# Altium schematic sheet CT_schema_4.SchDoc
size 312 x 289 mm
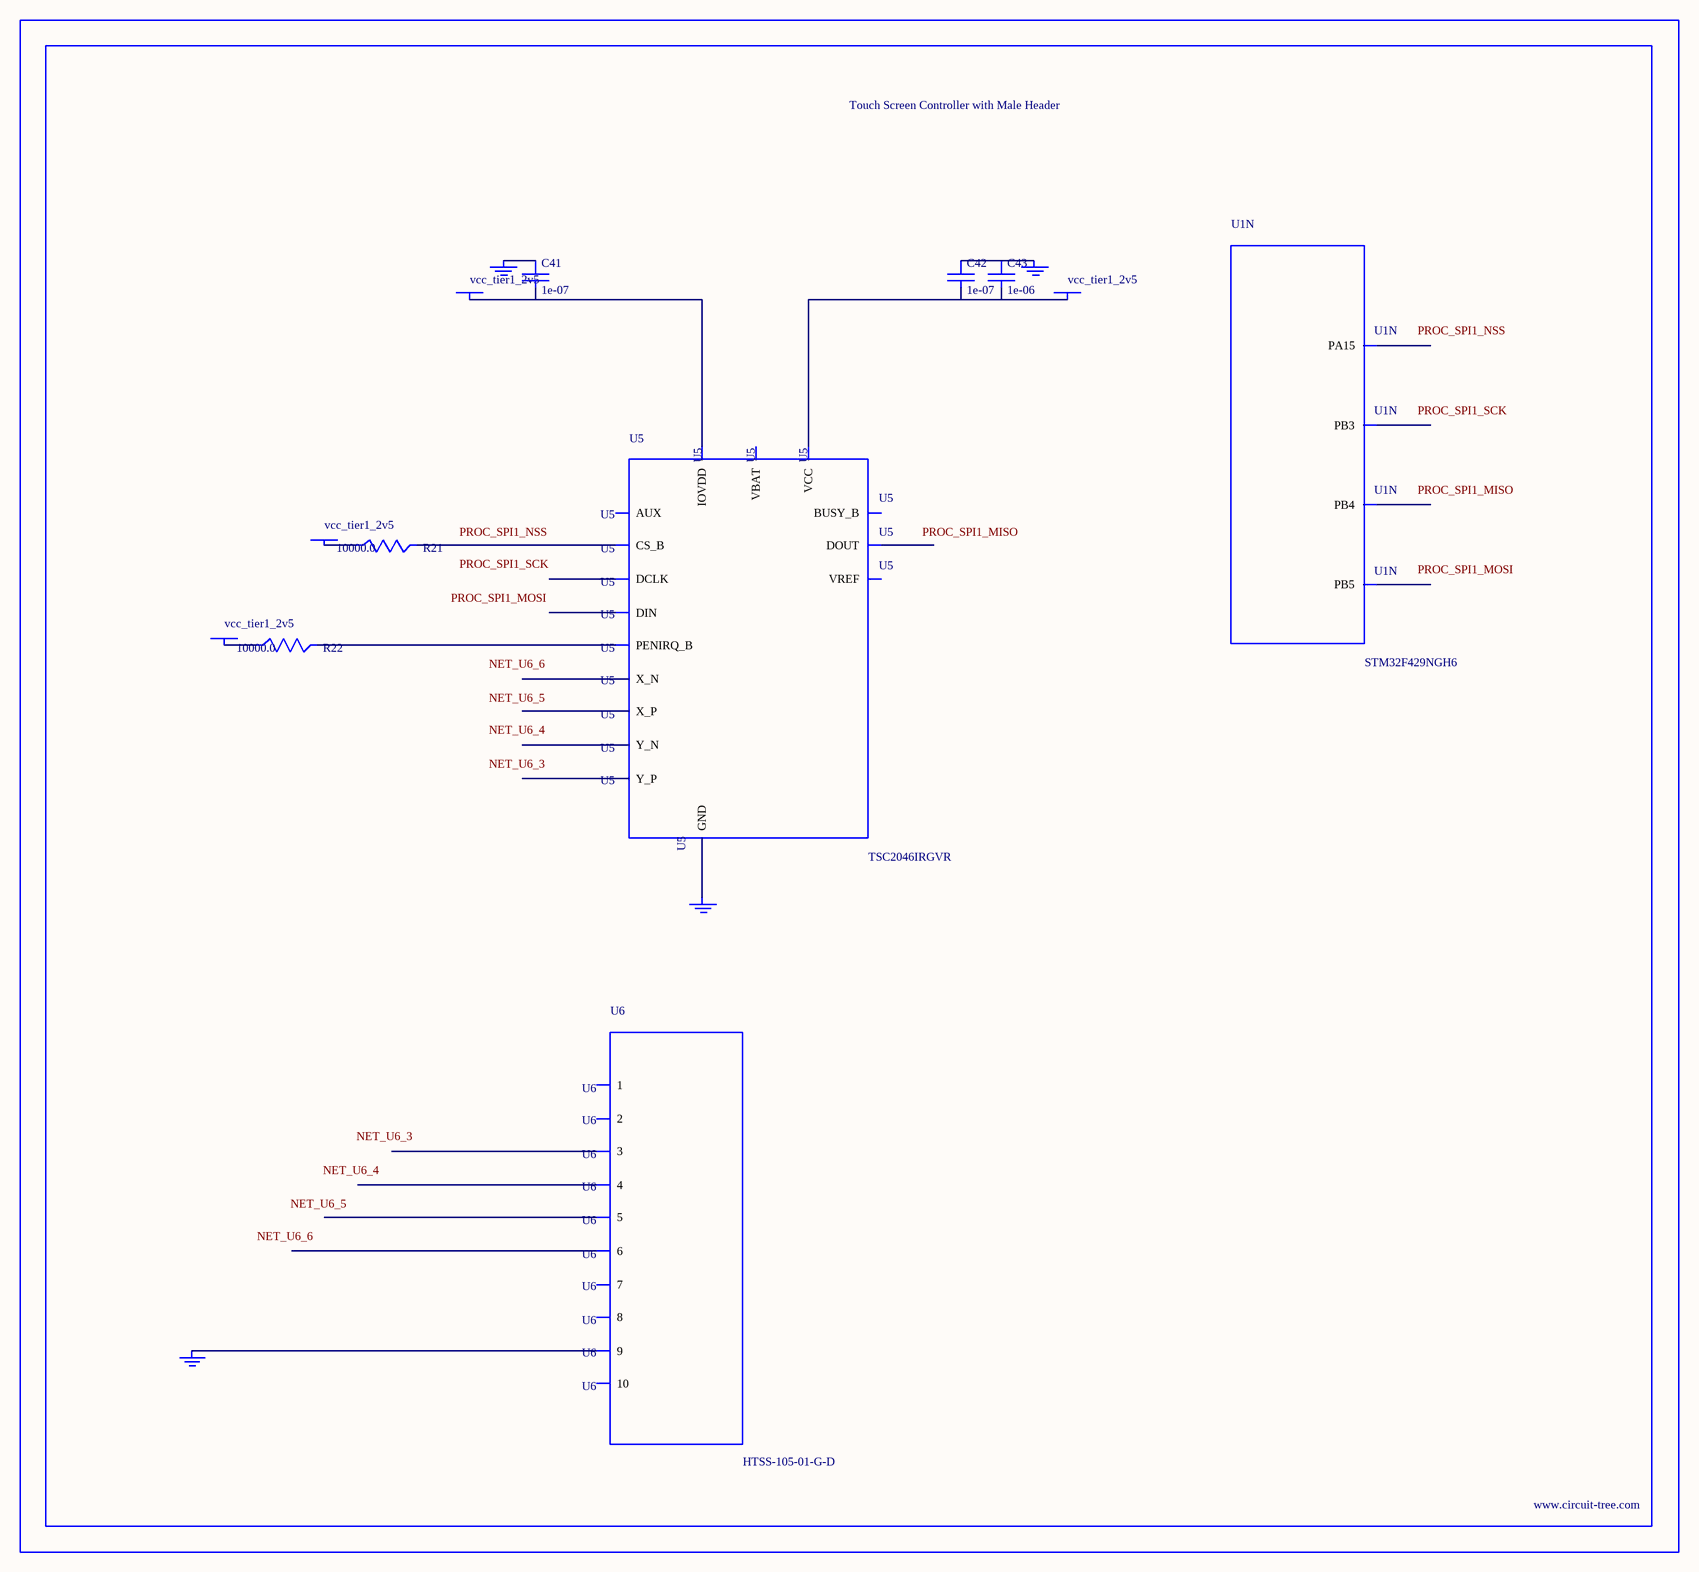
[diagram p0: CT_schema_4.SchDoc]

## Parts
BORDER3  (no value)
C41  1e-07  [C0402]
C42  1e-07  [C0402]
C43  1e-06  [C0603]
GND_INSTANCE_3_0  (no value)
GND_INSTANCE_3_1  (no value)
GND_INSTANCE_3_2  (no value)
GND_INSTANCE_3_3  (no value)
POWER_INSTANCE_3_0  vcc_tier1_2v5
POWER_INSTANCE_3_1  vcc_tier1_2v5
POWER_INSTANCE_3_2  vcc_tier1_2v5
POWER_INSTANCE_3_3  vcc_tier1_2v5
R21  10000.0  [R0603]
R22  10000.0  [R0603]
U1  STM32F429NGH6  [TFBGA216]  (part N of 16)
U5  TSC2046IRGVR  [VQFN-16]
U6  HTSS-105-01-G-D  [HTSS-105-01-G-D]

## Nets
NetC41_1: C41.1 GND_INSTANCE_3_1.0(GND)
NetC41_2: C41.2 POWER_INSTANCE_3_2.0(PWR) U5.14(IOVDD)
NetC42_1: C42.1 C43.1 GND_INSTANCE_3_0.0(GND)
NetC42_2: C42.2 C43.2 POWER_INSTANCE_3_1.0(PWR) U5.5(VCC)
NetGND_INSTANCE_3_2_0: GND_INSTANCE_3_2.0(GND) U5.10(GND)
NetGND_INSTANCE_3_3_0: GND_INSTANCE_3_3.0(GND) U6.9
NetPOWER_INSTANCE_3_0_0: POWER_INSTANCE_3_0.0(PWR) R21.1
NetPOWER_INSTANCE_3_3_0: POWER_INSTANCE_3_3.0(PWR) R22.1
NetR21_2: R21.2 U5.3(CS_B)
NetR22_2: R22.2 U5.15(PENIRQ_B)

Not connected (* = marked no-connect by the designer): U1 A8(PB5) A9(PB4) A10(PB3) A13(PA15); U5 1(BUSY_B) 2(DIN) 4(DCLK) 6(X_P) 7(Y_P) 8(X_N) 9(Y_N) 11(VBAT) 12(AUX) 13(VREF) 16(DOUT); U6 1 2 3 4 5 6 7 8 10

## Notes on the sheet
- Labels drawn without touching a wire or pin: NET_U6_3, NET_U6_4, NET_U6_5, NET_U6_6, PROC_SPI1_MISO, PROC_SPI1_MOSI, PROC_SPI1_NSS, PROC_SPI1_SCK

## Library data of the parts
BORDER3 = BORDER_PAGE3
C41 C42 = C0402C104K3RACTU
C43 = C0603C105K3RACTU
GND_INSTANCE_3_0-GND_INSTANCE_3_3 = GND
POWER_INSTANCE_3_0-POWER_INSTANCE_3_3 = PWR
R21 R22 = RC0603JR-0710KL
